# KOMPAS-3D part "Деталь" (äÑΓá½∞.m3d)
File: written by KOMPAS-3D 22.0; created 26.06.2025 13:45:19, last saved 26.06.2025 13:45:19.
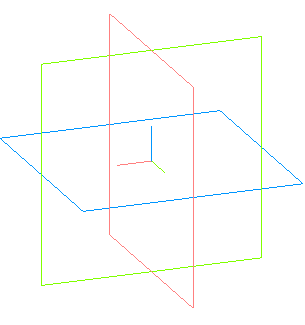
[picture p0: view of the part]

Document properties: Автор: Helen; Полное имя файла: D:\MY\WORK\MPEI\ППЭ_2025-2026\Варианты\Вар 6 СБ\Деталь.m3d

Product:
- Part/product: Деталь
